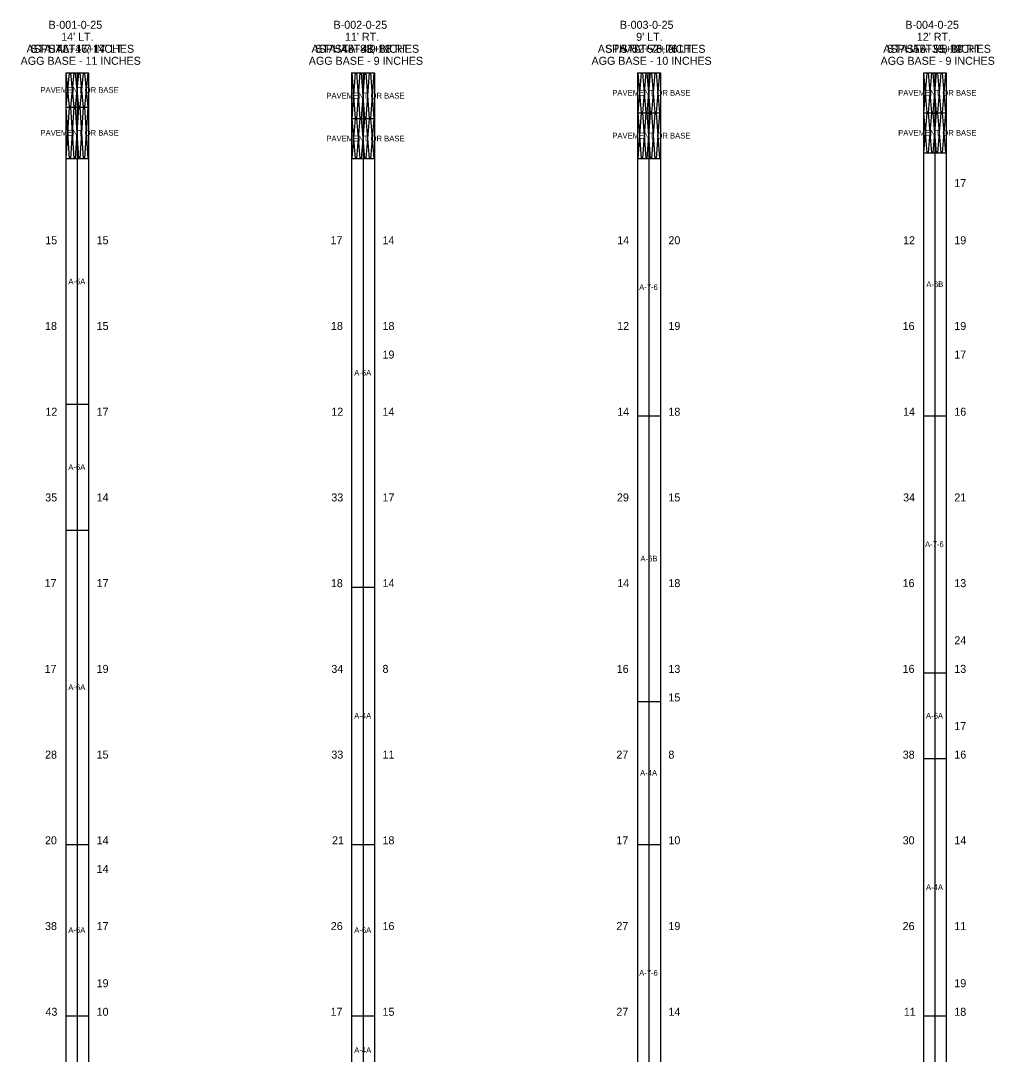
# Model space of a CAD drawing. Extents: x -1.2 to 16, y -0.9 to 35.
# Drawn here: x -0.99 to 16.04, y 16.93 to 35.01 of the extents above; entities that cross this region are included whole.
import ezdxf

# ---------------------------------------------------------------- set-up
doc = ezdxf.new("R2010")
doc.units = 0
for name, color, linetype in [('GT_Project_Soil_Boring', 7, 'Continuous'), ('GT_Project_Soil_Layers', 7, 'Continuous'), ('GT_Project_Text', 7, 'Continuous'), ('GT_Project_Text_2', 7, 'Continuous'), ('GT_Project_Text_3', 7, 'Continuous'), ('SC_Scratch1', 7, 'Continuous'), ('SC_Scratch3', 7, 'Continuous')]:
    doc.layers.add(name, color=color, linetype=linetype)

msp = doc.modelspace()

# ---------------------------------------------------------------- linework, layer by layer
at = {"layer": 'GT_Project_Soil_Boring'}
for p, q in [((-0.2, 34.1), (0.2, 34.1)), ((-0.2, 34.1), (-0.2, 10.8)), ((0, 34.1), (0, 10.8)), ((0.2, 34.1), (0.2, 10.8)), ((4.8, 34.1), (5.2, 34.1)), ((4.8, 34.1), (4.8, 3.4)), ((5, 34.1), (5, 3.4)), ((5.2, 34.1), (5.2, 3.4)), ((9.8, 34.1), (10.2, 34.1)), ((9.8, 34.1), (9.8, 0)), ((10, 34.1), (10, 0)), ((10.2, 34.1), (10.2, 0)), ((14.8, 34.1), (15.2, 34.1)), ((14.8, 34.1), (14.8, 4.1)), ((15, 34.1), (15, 4.1)), ((15.2, 34.1), (15.2, 4.1)), ((-0.2, 33.5), (0.2, 33.5)), ((4.8, 33.3), (5.2, 33.3)), ((9.8, 33.4), (10.2, 33.4)), ((14.8, 33.4), (15.2, 33.4)), ((-0.2, 32.6), (0.2, 32.6)), ((4.8, 32.6), (5.2, 32.6)), ((9.8, 32.6), (10.2, 32.6)), ((14.8, 32.7), (15.2, 32.7)), ((-0.2, 28.3), (0.2, 28.3)), ((9.8, 28.1), (10.2, 28.1)), ((14.8, 28.1), (15.2, 28.1)), ((-0.2, 26.1), (0.2, 26.1)), ((4.8, 25.1), (5.2, 25.1)), ((14.8, 23.6), (15.2, 23.6)), ((9.8, 23.1), (10.2, 23.1)), ((14.8, 22.1), (15.2, 22.1)), ((-0.2, 20.6), (0.2, 20.6)), ((4.8, 20.6), (5.2, 20.6)), ((9.8, 20.6), (10.2, 20.6)), ((-0.2, 17.6), (0.2, 17.6)), ((4.8, 17.6), (5.2, 17.6)), ((14.8, 17.6), (15.2, 17.6))]:
    msp.add_line(p, q, dxfattribs=at)
at = {"layer": 'GT_Project_Soil_Layers'}
for p, q in [((-0.191, 33.5), (-0.133, 34.1)), ((-0.133, 33.5), (-0.191, 34.1)), ((-0.11, 33.5), (-0.052, 34.1)), ((-0.052, 33.5), (-0.11, 34.1)), ((-0.029, 33.5), (0.029, 34.1)), ((0.029, 33.5), (-0.029, 34.1)), ((0.052, 33.5), (0.11, 34.1)), ((0.11, 33.5), (0.052, 34.1)), ((0.133, 33.5), (0.191, 34.1)), ((0.191, 33.5), (0.133, 34.1)), ((4.809, 33.3), (4.867, 34.1)), ((4.867, 33.3), (4.809, 34.1)), ((4.89, 33.3), (4.948, 34.1)), ((4.948, 33.3), (4.89, 34.1)), ((4.971, 33.3), (5.029, 34.1)), ((5.029, 33.3), (4.971, 34.1)), ((5.052, 33.3), (5.11, 34.1)), ((5.11, 33.3), (5.052, 34.1)), ((5.133, 33.3), (5.191, 34.1)), ((5.191, 33.3), (5.133, 34.1)), ((9.809, 33.4), (9.867, 34.1)), ((9.867, 33.4), (9.809, 34.1)), ((9.89, 33.4), (9.948, 34.1)), ((9.948, 33.4), (9.89, 34.1)), ((9.971, 33.4), (10.029, 34.1)), ((10.029, 33.4), (9.971, 34.1)), ((10.052, 33.4), (10.11, 34.1)), ((10.11, 33.4), (10.052, 34.1)), ((10.133, 33.4), (10.191, 34.1)), ((10.191, 33.4), (10.133, 34.1)), ((14.809, 33.4), (14.867, 34.1)), ((14.867, 33.4), (14.809, 34.1)), ((14.89, 33.4), (14.948, 34.1)), ((14.948, 33.4), (14.89, 34.1)), ((14.971, 33.4), (15.029, 34.1)), ((15.029, 33.4), (14.971, 34.1)), ((15.052, 33.4), (15.11, 34.1)), ((15.11, 33.4), (15.052, 34.1)), ((15.133, 33.4), (15.191, 34.1)), ((15.191, 33.4), (15.133, 34.1)), ((-0.2, 33.5), (-0.2, 33.5)), ((-0.191, 32.6), (-0.133, 33.5)), ((-0.133, 32.6), (-0.191, 33.5)), ((-0.11, 32.6), (-0.052, 33.5)), ((-0.052, 32.6), (-0.11, 33.5)), ((-0.029, 32.6), (0.029, 33.5)), ((0.029, 32.6), (-0.029, 33.5)), ((0.052, 32.6), (0.11, 33.5)), ((0.11, 32.6), (0.052, 33.5)), ((0.133, 32.6), (0.191, 33.5)), ((0.191, 32.6), (0.133, 33.5)), ((4.8, 33.3), (4.8, 33.3)), ((4.809, 32.6), (4.867, 33.3)), ((4.867, 32.6), (4.809, 33.3)), ((4.89, 32.6), (4.948, 33.3)), ((4.948, 32.6), (4.89, 33.3)), ((4.971, 32.6), (5.029, 33.3)), ((5.029, 32.6), (4.971, 33.3)), ((5.052, 32.6), (5.11, 33.3)), ((5.11, 32.6), (5.052, 33.3)), ((5.133, 32.6), (5.191, 33.3)), ((5.191, 32.6), (5.133, 33.3)), ((9.8, 33.4), (9.8, 33.4)), ((9.809, 32.6), (9.867, 33.4)), ((9.867, 32.6), (9.809, 33.4)), ((9.89, 32.6), (9.948, 33.4)), ((9.948, 32.6), (9.89, 33.4)), ((9.971, 32.6), (10.029, 33.4)), ((10.029, 32.6), (9.971, 33.4)), ((10.052, 32.6), (10.11, 33.4)), ((10.11, 32.6), (10.052, 33.4)), ((10.133, 32.6), (10.191, 33.4)), ((10.191, 32.6), (10.133, 33.4)), ((14.8, 33.4), (14.8, 33.4)), ((14.809, 32.7), (14.867, 33.4)), ((14.867, 32.7), (14.809, 33.4)), ((14.89, 32.7), (14.948, 33.4)), ((14.948, 32.7), (14.89, 33.4)), ((14.971, 32.7), (15.029, 33.4)), ((15.029, 32.7), (14.971, 33.4)), ((15.052, 32.7), (15.11, 33.4)), ((15.11, 32.7), (15.052, 33.4)), ((15.133, 32.7), (15.191, 33.4)), ((15.191, 32.7), (15.133, 33.4)), ((-0.2, 32.6), (-0.2, 32.6)), ((4.8, 32.6), (4.8, 32.6)), ((9.8, 32.6), (9.8, 32.6)), ((14.8, 32.7), (14.8, 32.7))]:
    msp.add_line(p, q, dxfattribs=at)

# ---------------------------------------------------------------- texts
at = {"layer": 'GT_Project_Text'}
for s, p in [('B-001-0-25', (-0.5, 34.87)), ('B-002-0-25', (4.484, 34.87)), ('B-003-0-25', (9.492, 34.87)), ('B-004-0-25', (14.484, 34.87)), ('ASPHALT - 7 INCHES', (-0.887, 34.45)), ('ASPHALT - 9 INCHES', (4.097, 34.45)), ('ASPHALT - 8 INCHES', (9.105, 34.45)), ('ASPHALT - 8 INCHES', (14.097, 34.45)), ('AGG BASE - 11 INCHES', (-0.989, 34.24)), ('AGG BASE - 9 INCHES', (4.051, 34.24)), ('AGG BASE - 10 INCHES', (8.995, 34.24)), ('AGG BASE - 9 INCHES', (14.051, 34.24)), ('17', (15.34, 32.1)), ('15', (-0.559, 31.1)), ('15', (0.34, 31.1)), ('17', (4.43, 31.1)), ('14', (5.34, 31.1)), ('14', (9.445, 31.1)), ('20', (10.34, 31.1)), ('12', (14.444, 31.1)), ('19', (15.34, 31.1)), ('18', (-0.562, 29.6)), ('15', (0.34, 29.6)), ('18', (4.438, 29.6)), ('18', (5.34, 29.6)), ('12', (9.444, 29.6)), ('19', (10.34, 29.6)), ('16', (14.436, 29.6)), ('19', (15.34, 29.6)), ('19', (5.34, 29.1)), ('17', (15.34, 29.1)), ('12', (-0.556, 28.1)), ('17', (0.34, 28.1)), ('12', (4.444, 28.1)), ('14', (5.34, 28.1)), ('14', (9.445, 28.1)), ('18', (10.34, 28.1)), ('14', (14.445, 28.1)), ('16', (15.34, 28.1)), ('35', (-0.559, 26.6)), ('14', (0.34, 26.6)), ('33', (4.445, 26.6)), ('17', (5.34, 26.6)), ('29', (9.44, 26.6)), ('15', (10.34, 26.6)), ('34', (14.445, 26.6)), ('21', (15.34, 26.6)), ('17', (-0.57, 25.1)), ('17', (0.34, 25.1)), ('18', (4.438, 25.1)), ('14', (5.34, 25.1)), ('14', (9.445, 25.1)), ('18', (10.34, 25.1)), ('16', (14.436, 25.1)), ('13', (15.34, 25.1)), ('24', (15.34, 24.1)), ('17', (-0.57, 23.6)), ('19', (0.34, 23.6)), ('34', (4.445, 23.6)), ('8', (5.34, 23.6)), ('16', (9.436, 23.6)), ('13', (10.34, 23.6)), ('16', (14.436, 23.6)), ('13', (15.34, 23.6)), ('15', (10.34, 23.1)), ('17', (15.34, 22.6)), ('28', (-0.562, 22.1)), ('15', (0.34, 22.1)), ('33', (4.445, 22.1)), ('11', (5.34, 22.1)), ('27', (9.43, 22.1)), ('8', (10.34, 22.1)), ('38', (14.438, 22.1)), ('16', (15.34, 22.1)), ('20', (-0.563, 20.6)), ('14', (0.34, 20.6)), ('21', (4.457, 20.6)), ('18', (5.34, 20.6)), ('17', (9.43, 20.6)), ('10', (10.34, 20.6)), ('30', (14.437, 20.6)), ('14', (15.34, 20.6)), ('14', (0.34, 20.1)), ('38', (-0.562, 19.1)), ('17', (0.34, 19.1)), ('26', (4.436, 19.1)), ('16', (5.34, 19.1)), ('27', (9.43, 19.1)), ('19', (10.34, 19.1)), ('26', (14.436, 19.1)), ('11', (15.34, 19.1)), ('19', (0.34, 18.1)), ('19', (15.34, 18.1)), ('43', (-0.555, 17.6)), ('10', (0.34, 17.6)), ('17', (4.43, 17.6)), ('15', (5.34, 17.6)), ('27', (9.43, 17.6)), ('14', (10.34, 17.6)), ('11', (14.457, 17.6)), ('18', (15.34, 17.6))]:
    msp.add_text(s, height=0.14, dxfattribs=at).set_placement(p)
at = {"layer": 'GT_Project_Text_2'}
for s, p in [("14' LT.", (-0.28, 34.66)), ("11' RT.", (4.684, 34.66)), ("9' LT.", (9.776, 34.66)), ("12' RT.", (14.684, 34.66))]:
    msp.add_text(s, height=0.14, dxfattribs=at).set_placement(p)
at = {"layer": 'GT_Project_Text_3'}
for s, p in [('STA. 46+17', (-0.501, 34.45)), ('STA. 48+88', (4.503, 34.45)), ('STA. 52+76', (9.502, 34.45)), ('STA. 55+39', (14.504, 34.45))]:
    msp.add_text(s, height=0.14, dxfattribs=at).set_placement(p)
at = {"layer": 'SC_Scratch1'}
for s, p in [('PAVEMENT OR BASE', (-0.642, 33.75)), ('PAVEMENT OR BASE', (4.358, 33.65)), ('PAVEMENT OR BASE', (9.358, 33.7)), ('PAVEMENT OR BASE', (14.358, 33.7)), ('PAVEMENT OR BASE', (-0.642, 33)), ('PAVEMENT OR BASE', (14.358, 33)), ('PAVEMENT OR BASE', (4.358, 32.9)), ('PAVEMENT OR BASE', (9.358, 32.95)), ('A-6A', (-0.155, 30.4)), ('A-7-6', (9.828, 30.3)), ('A-6B', (14.85, 30.35)), ('A-6A', (4.845, 28.8)), ('A-6A', (-0.155, 27.15)), ('A-7-6', (14.828, 25.8)), ('A-6B', (9.85, 25.55)), ('A-6A', (-0.155, 23.3)), ('A-4A', (4.845, 22.8)), ('A-6A', (14.845, 22.8)), ('A-4A', (9.845, 21.8)), ('A-4A', (14.845, 19.8)), ('A-6A', (-0.155, 19.05)), ('A-6A', (4.845, 19.05)), ('A-7-6', (9.828, 18.3)), ('A-4A', (4.845, 16.95))]:
    msp.add_text(s, height=0.1, dxfattribs=at).set_placement(p)
at = {"layer": 'SC_Scratch3'}
for s, p in [("STA. 46+17, 14' LT.", (-0.819, 34.45)), ("STA. 48+88, 11' RT.", (4.161, 34.45)), ("STA. 52+76, 9' LT.", (9.237, 34.45)), ("STA. 55+39, 12' RT.", (14.161, 34.45))]:
    msp.add_text(s, height=0.14, dxfattribs=at).set_placement(p)

doc.saveas('drawing.dxf')
